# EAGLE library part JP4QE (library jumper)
JUMPER
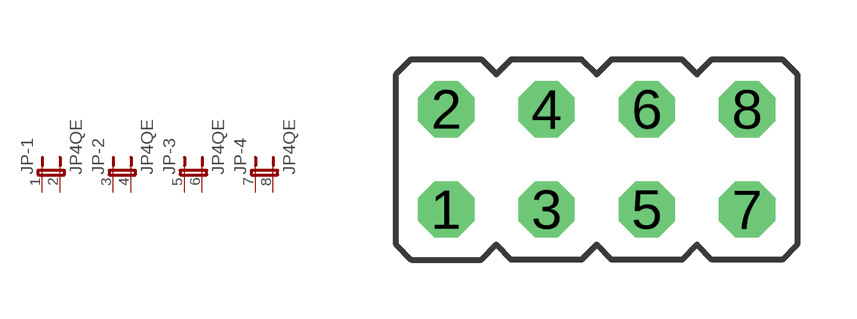
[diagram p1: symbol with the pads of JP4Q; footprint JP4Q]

Designator prefix JP; gates -1=JP2E -2=JP2E -3=JP2E -4=JP2E

## JP4QE  [JP4Q]
1  -1:1  pas
2  -1:2  pas
3  -2:1  pas
4  -2:2  pas
5  -3:1  pas
6  -3:2  pas
7  -4:1  pas
8  -4:2  pas

## Footprint JP4Q (pad centres in mm)
JUMPER
drill 0.914 octagon: 1 -3.81,-1.27; 2 -3.81,1.27; 3 -1.27,-1.27; 4 -1.27,1.27; 5 1.27,-1.27; 6 1.27,1.27; 7 3.81,-1.27; 8 3.81,1.27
